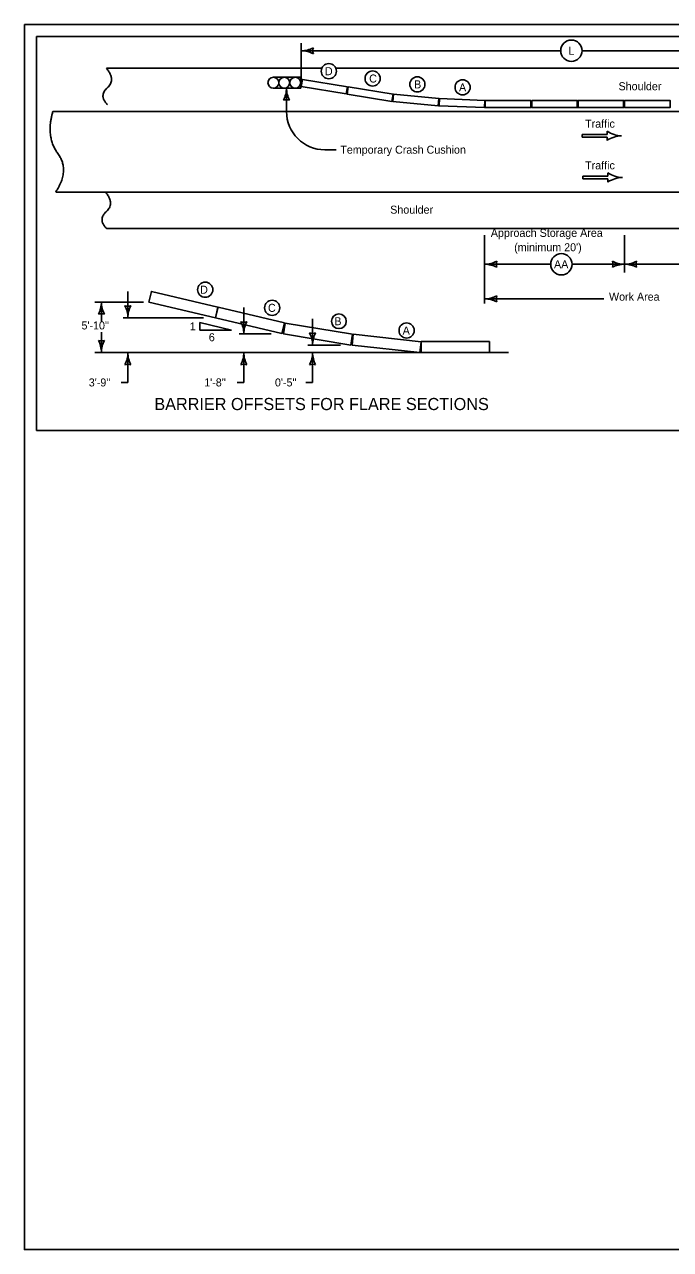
# Model space of a CAD drawing. Extents: x 6410 to 81668, y 3928 to 11667.
# Drawn here: x 13733 to 14797, y 7924 to 9944 of the extents above; entities that cross this region are included whole.
import ezdxf

# ---------------------------------------------------------------- set-up
doc = ezdxf.new("R2010")
doc.units = 0
doc.layers.add('dsnStdSection', color=7, linetype='Continuous')
doc.layers.add('Level 8', color=7, linetype='Continuous')

msp = doc.modelspace()

# ---------------------------------------------------------------- linework, layer by layer
at = {"layer": 'dsnStdSection'}
for p, q in [((13752.2, 9924.4), (16857.2, 9924.4)), ((13752.2, 9274.4), (13752.2, 9924.4)), ((14188.6, 9913.5), (14188.6, 9840.9)), ((14188.6, 9900.7), (14616.4, 9900.7)), ((14651.5, 9900.7), (15092, 9900.7)), ((13867.5, 9871.8), (14221.2, 9871.8)), ((14246.4, 9871.8), (14996, 9871.8)), ((14142.7, 9857), (14187.7, 9857)), ((14187.7, 9839), (14142.7, 9839)), ((14164.3, 9839.4), (14164.3, 9800.7)), ((14186.5, 9844.7), (14187.8, 9844.4)), ((14187.7, 9857), (14187.7, 9839)), ((14188.3, 9841), (14188.3, 9841)), ((13779.2, 9800.7), (15026, 9800.7)), ((14692.7, 9762.8), (14651.4, 9762.8)), ((14651.4, 9762.8), (14651.4, 9758.3)), ((14651.4, 9758.3), (14692.7, 9758.3)), ((14692.7, 9768), (14692.7, 9762.8)), ((14692.7, 9758.3), (14692.7, 9753)), ((14716.6, 9760.5), (14716.6, 9760.5)), ((14246.3, 9737.4), (14227.6, 9737.4)), ((14694.2, 9699.3), (14694.2, 9694)), ((14694.2, 9694), (14652.9, 9694)), ((14652.9, 9694), (14652.9, 9689.5)), ((14652.9, 9689.5), (14694.2, 9689.5)), ((14694.2, 9689.5), (14694.2, 9684.3)), ((14718.1, 9691.8), (14718.1, 9691.8)), ((13783.9, 9667.8), (15026, 9667.8)), ((13867.5, 9607.8), (14996, 9607.8)), ((14490.8, 9596.5), (14490.8, 9484.1)), ((14721.5, 9596.5), (14721.5, 9535.3)), ((14490.8, 9548.7), (14599.8, 9548.7)), ((14635.1, 9548.7), (14721.5, 9548.7)), ((14721.5, 9548.7), (14854.3, 9548.7)), ((13902.9, 9503.8), (13902.9, 9460.4)), ((13928.8, 9486.3), (13848.4, 9486.3)), ((13859.3, 9486.3), (13859.3, 9452.9)), ((14094, 9477.4), (14094, 9434)), ((14490.8, 9491.6), (14687.2, 9491.6)), ((14027.7, 9460.4), (13895.1, 9460.4)), ((14207.3, 9458.9), (14207.3, 9415.4)), ((13859.3, 9436.5), (13859.3, 9403.1)), ((14073.9, 9440), (14021.3, 9452.4)), ((14021.3, 9452.4), (14021.3, 9440)), ((14021.3, 9440), (14073.9, 9440)), ((14139, 9434), (14086.3, 9434)), ((14253.2, 9415.4), (14199.5, 9415.4)), ((14530.3, 9403.1), (13848.4, 9403.1)), ((13902.9, 9403.1), (13902.9, 9353.8)), ((14094, 9403.1), (14094, 9353.8)), ((14207.3, 9403.1), (14207.3, 9376.1)), ((14207.3, 9376.1), (14207.3, 9353.8)), ((13902.9, 9353.8), (13891.7, 9353.8)), ((14094, 9353.8), (14082.9, 9353.8)), ((14207.3, 9353.8), (14196.1, 9353.8)), ((16857.2, 9274.4), (13752.2, 9274.4))]:
    msp.add_line(p, q, dxfattribs=at)
for points in [[(14264.6, 9841.4), (14190.5, 9853.6), (14188.6, 9841.7), (14262.6, 9829.6)], [(14340.1, 9829.1), (14266, 9841.2), (14264.1, 9829.4), (14338.1, 9817.2)], [(14415.5, 9821.8), (14340.8, 9828.9), (14339.7, 9817), (14414.3, 9809.9)], [(14491.2, 9818.9), (14416.3, 9821.9), (14415.8, 9809.9), (14490.8, 9806.9)], [(14492, 9818.9), (14567, 9818.9), (14567, 9806.9), (14492, 9806.9)], [(14568.5, 9818.9), (14643.5, 9818.9), (14643.5, 9806.9), (14568.5, 9806.9)], [(14645, 9818.9), (14720, 9818.9), (14720, 9806.9), (14645, 9806.9)], [(14721.5, 9818.9), (14796.5, 9818.9), (14796.5, 9806.9), (14721.5, 9806.9)], [(14051.2, 9478), (13941.8, 9503.9), (13937.6, 9486.4), (14047.1, 9460.5)], [(14161, 9452), (14051.6, 9477.9), (14047.4, 9460.4), (14156.9, 9434.5)], [(14273.1, 9433.3), (14162.2, 9451.7), (14159.2, 9434), (14270.2, 9415.5)], [(14386.2, 9421), (14274.4, 9433.3), (14272.4, 9415.4), (14384.2, 9403.1)], [(14498.7, 9421.2), (14386.2, 9421.1), (14386.2, 9403.1), (14498.7, 9403.2)]]:
    msp.add_lwpolyline(points, close=True, dxfattribs=at)
for centre, radius in [((14633.9, 9900.7), 17.6), ((14234.1, 9867), 12.5), ((14306.3, 9854.9), 12.5), ((14380, 9845.3), 12.5), ((14142.7, 9848), 9), ((14142.7, 9848), 9), ((14160.7, 9848), 9), ((14160.7, 9848), 9), ((14178.7, 9848), 9), ((14178.7, 9848), 9), ((14454.6, 9840.4), 12.5), ((14617.5, 9548.7), 17.6), ((14030.4, 9506.7), 12.5), ((14140.7, 9476.8), 12.5), ((14250.7, 9454.7), 12.2), ((14362.3, 9439.4), 12.5)]:
    msp.add_circle(centre, radius, dxfattribs=at)
for centre, radius, start, end in [((14188.6, 9943.2), 42.5, 270, 298.0725), ((14188.6, 9858.2), 42.5, 61.9275, 90), ((14224.2, 9900.7), 16.4, 162.2666, 197.7334), ((14121.8, 9839.2), 42.5, 331.9275, 360), ((14206.8, 9839.2), 42.5, 180, 208.0725), ((14164.3, 9803.5), 16.4, 72.2666, 107.7334), ((14227.6, 9800.7), 63.3, 180, 270), ((14718.6, 9808.8), 48.4, 237.618, 267.648), ((14718.6, 9712.2), 48.4, 92.352, 122.382), ((14720.1, 9740.1), 48.4, 237.618, 267.648), ((14720.1, 9643.5), 48.4, 92.352, 122.382), ((14490.8, 9591.2), 42.5, 270, 298.0725), ((14490.8, 9506.2), 42.5, 61.9275, 90), ((14526.4, 9548.7), 16.4, 162.2666, 197.7334), ((14685.8, 9548.7), 16.4, 342.2666, 17.7333), ((14721.5, 9591.2), 42.5, 241.9275, 270), ((14721.5, 9506.2), 42.5, 90, 118.0725), ((14721.5, 9591.2), 42.5, 270, 298.0725), ((14721.5, 9506.2), 42.5, 61.9275, 90), ((14757.1, 9548.7), 16.4, 162.2666, 197.7334), ((14490.8, 9534.1), 42.5, 270, 298.0725), ((14526.4, 9491.6), 16.4, 162.2666, 197.7334), ((13816.8, 9486.3), 42.5, 331.9275, 0), ((13901.8, 9486.3), 42.5, 180, 208.0725), ((13902.9, 9496), 16.4, 252.2666, 287.7334), ((13860.4, 9460.4), 42.5, 0, 28.0725), ((13945.4, 9460.4), 42.5, 151.9275, 180), ((14490.8, 9449.1), 42.5, 61.9275, 90), ((13859.3, 9450.7), 16.4, 72.2666, 107.7334), ((14094, 9469.6), 16.4, 252.2666, 287.7334), ((14051.5, 9434), 42.5, 0, 28.0725), ((14136.5, 9434), 42.5, 151.9275, 180), ((14207.3, 9451), 16.4, 252.2666, 287.7334), ((14164.8, 9415.4), 42.5, 0, 28.0725), ((14249.8, 9415.4), 42.5, 151.9275, 180), ((13859.3, 9438.7), 16.4, 252.2666, 287.7334), ((13816.8, 9403.1), 42.5, 0, 28.0725), ((13901.8, 9403.1), 42.5, 151.9275, 180), ((13860.4, 9403.1), 42.5, 331.9275, 0), ((13945.4, 9403.1), 42.5, 180, 208.0725), ((14051.5, 9403.1), 42.5, 331.9275, 0), ((14136.5, 9403.1), 42.5, 180, 208.0725), ((14164.8, 9403.1), 42.5, 331.9275, 0), ((14249.8, 9403.1), 42.5, 180, 208.0725), ((13902.9, 9367.4), 16.4, 72.2666, 107.7334), ((14094, 9367.4), 16.4, 72.2666, 107.7334), ((14207.3, 9367.4), 16.4, 72.2666, 107.7334)]:
    msp.add_arc(centre, radius, start, end, dxfattribs=at)
for points in [[(13867.5, 9871.8), (13883.5, 9852.5), (13854.6, 9826.9), (13869.1, 9811.8)], [(13779.2, 9800.7), (13767.2, 9758.9), (13807.8, 9703.7), (13783.9, 9667.8)], [(13865.9, 9667.8), (13881.9, 9648.4), (13853, 9622.8), (13867.5, 9607.8)]]:
    msp.add_open_spline(points, degree=2, dxfattribs=at)
at = {"layer": 'Level 8'}
msp.add_lwpolyline([(13732.5, 9944), (16867.5, 9944), (16867.5, 7924), (13732.5, 7924)], close=True, dxfattribs=at)

# ---------------------------------------------------------------- texts
at = {"layer": 'dsnStdSection'}
for s, height, p in [('L', 13.2, (14629, 9894.1)), ('D', 13.2, (14227.7, 9860.4)), ('C', 13.2, (14300.6, 9848.3)), ('B', 13.2, (14374.6, 9838.7)), ('A', 13.2, (14448.7, 9833.8)), ('Shoulder', 13.2, (14711.6, 9835.6)), ('Traffic', 13.2, (14656.5, 9773.9)), ('Temporary Crash Cushion', 13.2, (14253, 9731)), ('Traffic', 13.2, (14656.5, 9705.2)), ('Shoulder', 13.2, (14335.3, 9632.1)), ('Approach Storage Area', 13.2, (14501.1, 9593.8)), ("(minimum 20')", 13.2, (14539.6, 9570.1)), ('AA', 13.2, (14605.3, 9542.1)), ('D', 13.2, (14022, 9500.1)), ('Work Area', 13.2, (14695.9, 9488.6)), ('C', 13.2, (14133.8, 9470.2)), ("5'-10''", 13.2, (13826.4, 9441.2)), ('B', 13.2, (14243.2, 9448.1)), ('1', 13.2, (14004.9, 9439.7)), ('6', 13.2, (14036.3, 9421.7)), ('A', 13.2, (14355.8, 9432.8)), ("3'-9''", 13.2, (13838.4, 9347.2)), ("1'-8''", 13.2, (14028.7, 9347.2)), ("0'-5''", 13.2, (14145.3, 9347.2)), ('BARRIER OFFSETS FOR FLARE SECTIONS', 20, (13946.5, 9308.2))]:
    msp.add_text(s, height=height, dxfattribs=at).set_placement(p)

doc.saveas('drawing.dxf')
